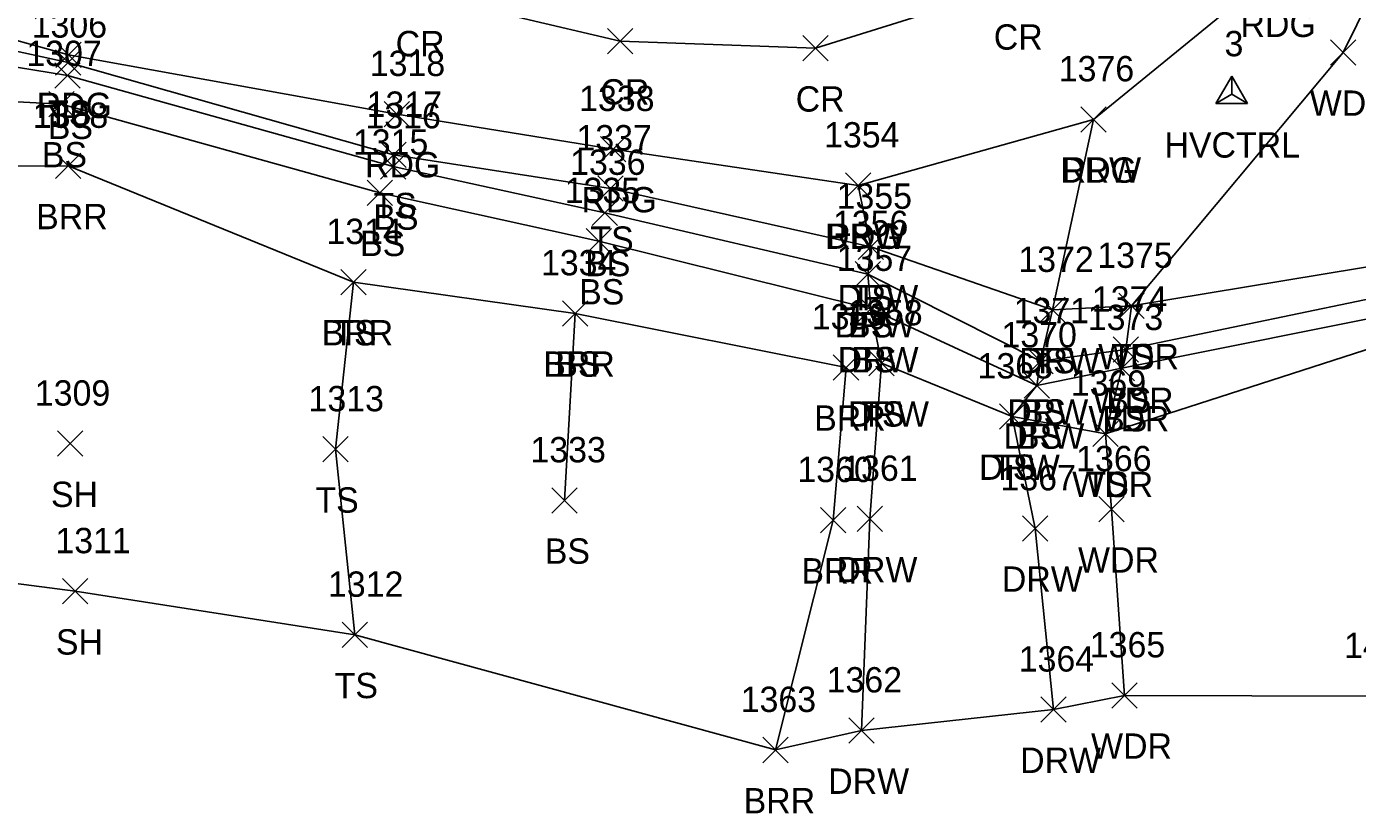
# Model space of a CAD drawing. Extents: x 1600281 to 1602254, y 862855 to 863227.
# Drawn here: x 1601927.2 to 1602032.3, y 862855.3 to 862917.4 of the extents above; entities that cross this region are included whole.
import ezdxf

# ---------------------------------------------------------------- set-up
doc = ezdxf.new("R2010")
doc.units = 0
for name, color, linetype in [('C_A', 7, 'Continuous'), ('C_I', 7, 'Continuous'), ('CPSM', 7, 'Continuous'), ('L_A', 7, 'Continuous'), ('L_I', 7, 'Continuous'), ('L_TIC', 7, 'Continuous'), ('LABL', 7, 'Continuous'), ('LAWA', 7, 'Continuous'), ('LELB', 7, 'Continuous'), ('LSOGP', 7, 'Continuous'), ('P_A', 7, 'Continuous'), ('P_I', 7, 'Continuous'), ('P_TIC', 7, 'Continuous'), ('PEU', 7, 'Continuous'), ('PRC', 7, 'Continuous'), ('R_A', 7, 'Continuous'), ('R_I', 7, 'Continuous'), ('R_TIC', 7, 'Continuous'), ('RDW', 7, 'Continuous')]:
    doc.layers.add(name, color=color, linetype=linetype)

msp = doc.modelspace()

# ---------------------------------------------------------------- linework, layer by layer
at = {"layer": 'CPSM'}
for p, q in [((1602021.09, 862911.32), (1602022.34, 862913.48)), ((1602023.59, 862911.32), (1602022.34, 862913.48)), ((1602022.34, 862912.04), (1602022.34, 862913.48)), ((1602021.09, 862911.32), (1602022.34, 862912.04)), ((1602022.34, 862912.04), (1602022.34, 862912.04)), ((1602022.34, 862912.04), (1602023.59, 862911.32)), ((1602021.09, 862911.32), (1602023.59, 862911.32))]:
    msp.add_line(p, q, dxfattribs=at)
at = {"layer": 'L_TIC'}
for points in [[(1602030.13, 862914.34), (1602032.13, 862916.34)], [(1602032.13, 862914.34), (1602030.13, 862916.34)], [(1601929.52, 862913.56), (1601931.52, 862915.56)], [(1601931.52, 862913.56), (1601929.52, 862915.56)], [(1601929.47, 862912.51), (1601931.47, 862914.51)], [(1601931.47, 862912.51), (1601929.47, 862914.51)], [(1601929, 862910.27), (1601931, 862912.27)], [(1601931, 862910.27), (1601929, 862912.27)], [(1601929.51, 862905.39), (1601931.51, 862907.39)], [(1601931.51, 862905.39), (1601929.51, 862907.39)], [(1601955.16, 862905.35), (1601957.16, 862907.35)], [(1601957.16, 862905.35), (1601955.16, 862907.35)], [(1601955.2, 862906.26), (1601957.2, 862908.26)], [(1601957.2, 862906.26), (1601955.2, 862908.26)], [(1601954.11, 862903.27), (1601956.11, 862905.27)], [(1601956.11, 862903.27), (1601954.11, 862905.27)], [(1601972.32, 862903.61), (1601974.32, 862905.61)], [(1601974.32, 862903.61), (1601972.32, 862905.61)], [(1601971.87, 862901.68), (1601973.87, 862903.68)], [(1601973.87, 862901.68), (1601971.87, 862903.68)], [(1601971.4, 862899.45), (1601973.4, 862901.45)], [(1601973.4, 862899.45), (1601971.4, 862901.45)], [(1601992.85, 862899), (1601994.85, 862901)], [(1601994.85, 862899), (1601992.85, 862901)], [(1601952.03, 862896.22), (1601954.03, 862898.22)], [(1601954.03, 862896.22), (1601952.03, 862898.22)], [(1601952.03, 862896.22), (1601954.03, 862898.22)], [(1601954.03, 862896.22), (1601952.03, 862898.22)], [(1601992.62, 862896.85), (1601994.62, 862898.85)], [(1601994.62, 862896.85), (1601992.62, 862898.85)], [(1601969.52, 862893.75), (1601971.52, 862895.75)], [(1601971.52, 862893.75), (1601969.52, 862895.75)], [(1601969.52, 862893.75), (1601971.52, 862895.75)], [(1601971.52, 862893.75), (1601969.52, 862895.75)], [(1601992.87, 862894.1), (1601994.87, 862896.1)], [(1601994.87, 862894.1), (1601992.87, 862896.1)], [(1602007.19, 862894.02), (1602009.19, 862896.02)], [(1602009.19, 862894.02), (1602007.19, 862896.02)], [(1602013.42, 862894.34), (1602015.42, 862896.34)], [(1602015.42, 862894.34), (1602013.42, 862896.34)], [(1602013.42, 862894.34), (1602015.42, 862896.34)], [(1602015.42, 862894.34), (1602013.42, 862896.34)], [(1602012.99, 862890.89), (1602014.99, 862892.89)], [(1602014.99, 862890.89), (1602012.99, 862892.89)], [(1602012.99, 862890.89), (1602014.99, 862892.89)], [(1602014.99, 862890.89), (1602012.99, 862892.89)], [(1601993.69, 862889.81), (1601995.69, 862891.81)], [(1601995.69, 862889.81), (1601993.69, 862891.81)], [(1602006.26, 862889.97), (1602008.26, 862891.97)], [(1602008.26, 862889.97), (1602006.26, 862891.97)], [(1601990.9, 862889.49), (1601992.9, 862891.49)], [(1601992.9, 862889.49), (1601990.9, 862891.49)], [(1602012.67, 862889.43), (1602014.67, 862891.43)], [(1602014.67, 862889.43), (1602012.67, 862891.43)], [(1602012.67, 862889.43), (1602014.67, 862891.43)], [(1602014.67, 862889.43), (1602012.67, 862891.43)], [(1602005.95, 862888.06), (1602007.95, 862890.06)], [(1602007.95, 862888.06), (1602005.95, 862890.06)], [(1602004.02, 862885.61), (1602006.02, 862887.61)], [(1602006.02, 862885.61), (1602004.02, 862887.61)], [(1601929.67, 862883.47), (1601931.67, 862885.47)], [(1601931.67, 862883.47), (1601929.67, 862885.47)], [(1602011.39, 862884.25), (1602013.39, 862886.25)], [(1602013.39, 862884.25), (1602011.39, 862886.25)], [(1602011.39, 862884.25), (1602013.39, 862886.25)], [(1602013.39, 862884.25), (1602011.39, 862886.25)], [(1601950.62, 862883.02), (1601952.62, 862885.02)], [(1601952.62, 862883.02), (1601950.62, 862885.02)], [(1601968.69, 862878.99), (1601970.69, 862880.99)], [(1601970.69, 862878.99), (1601968.69, 862880.99)], [(1602011.85, 862878.29), (1602013.85, 862880.29)], [(1602013.85, 862878.29), (1602011.85, 862880.29)], [(1601989.89, 862877.43), (1601991.89, 862879.43)], [(1601991.89, 862877.43), (1601989.89, 862879.43)], [(1601930.07, 862871.82), (1601932.07, 862873.82)], [(1601932.07, 862871.82), (1601930.07, 862873.82)], [(1601952.14, 862868.38), (1601954.14, 862870.38)], [(1601954.14, 862868.38), (1601952.14, 862870.38)], [(1602012.88, 862863.6), (1602014.88, 862865.6)], [(1602014.88, 862863.6), (1602012.88, 862865.6)], [(1601985.33, 862859.29), (1601987.33, 862861.29)], [(1601987.33, 862859.29), (1601985.33, 862861.29)]]:
    msp.add_lwpolyline(points, dxfattribs=at)
at = {"layer": 'LABL'}
msp.add_lwpolyline([(1601757.73, 862925.71), (1601782.73, 862922.12), (1601780.79, 862913), (1601791.17, 862907.66), (1601819.52, 862897.83), (1601840.22, 862897.63), (1601849.86, 862909.96), (1601871.21, 862909.53), (1601900.52, 862906.28), (1601930.51, 862906.39), (1601953.03, 862897.22), (1601970.52, 862894.75), (1601991.9, 862890.49), (1601990.89, 862878.43), (1601986.33, 862860.29)], dxfattribs=at)
at = {"layer": 'LAWA'}
msp.add_lwpolyline([(1602013.88, 862864.6), (1602012.85, 862879.29), (1602012.39, 862885.25), (1602013.67, 862890.43), (1602013.99, 862891.89), (1602014.42, 862895.34), (1602031.13, 862915.34), (1602041.82, 862937), (1602041.48, 862949.37), (1602043.12, 862970.37), (1602043.1, 862998.4), (1602042.78, 863006.72), (1602043.56, 863021.7), (1602048.72, 863030.45), (1602052.92, 863023.58), (1602057.07, 863015.5), (1602062.85, 863014.97)], dxfattribs=at)
at = {"layer": 'LELB'}
for points in [[(1601758.87, 862935.58), (1601794.57, 862931.04), (1601823.26, 862926.65), (1601871.56, 862921.03), (1601900.01, 862918.49), (1601930.47, 862913.51), (1601956.16, 862906.35), (1601972.87, 862902.68), (1601993.62, 862897.85), (1602007.26, 862890.97), (1602013.99, 862891.89), (1602036.74, 862896.62), (1602039.12, 862902.94), (1602042.65, 862913.22), (1602071.45, 862922.17), (1602077.73, 862924.94), (1602083, 862929.53), (1602079.85, 862943.1), (1602074.85, 862964.04), (1602072.57, 862980.37), (1602075.41, 862992.31), (1602081.73, 863011.09), (1602084.93, 863020.57), (1602086.17, 863023.52)], [(1601758.25, 862932.38), (1601793.25, 862926.87), (1601822.78, 862921.72), (1601870.88, 862915.2), (1601899.96, 862912.84), (1601930, 862911.27), (1601955.11, 862904.27), (1601972.4, 862900.45), (1601993.87, 862895.1), (1602006.95, 862889.06), (1602013.67, 862890.43), (1602037.38, 862895.19), (1602041.45, 862902.14), (1602044.34, 862911.83), (1602073.39, 862917.1), (1602080.57, 862918.06), (1602084.27, 862928.9), (1602082.1, 862942.17), (1602076.79, 862963.57), (1602077.84, 862979.48), (1602084.81, 862995.17), (1602084.83, 863009.34), (1602087.06, 863019.48), (1602088.42, 863022.64)], [(1601758.89, 862937.88), (1601795.07, 862933.9), (1601823.85, 862928.87), (1601870.34, 862922.92), (1601900.35, 862921.15), (1601930.52, 862914.56), (1601956.2, 862907.26), (1601973.32, 862904.61), (1601993.85, 862900), (1602008.19, 862895.02), (1602014.42, 862895.34), (1602035.61, 862898.84), (1602036.45, 862903.94), (1602042.39, 862916.03), (1602070.54, 862924.32), (1602075.87, 862928.13), (1602081.56, 862930.04), (1602078.85, 862942.66), (1602073.58, 862963.52), (1602071.23, 862980.75), (1602072.26, 862993.36), (1602076.69, 863007.7), (1602078.09, 863013.39), (1602083.85, 863020.87)], [(1601994.69, 862890.81), (1602005.02, 862886.61), (1602012.39, 862885.25), (1602036.93, 862893.17), (1602042.39, 862901.65), (1602044.79, 862907.83), (1602074.6, 862913.52), (1602080.81, 862915.53), (1602085.28, 862928.21), (1602083.54, 862943.15), (1602080.9, 862962.87), (1602080.76, 862979.18), (1602088.3, 862994.75), (1602086.85, 863009.16), (1602089.05, 863018.84)], [(1601953.14, 862869.38), (1601951.62, 862884.02), (1601953.03, 862897.22)], [(1601969.69, 862879.99), (1601970.52, 862894.75)]]:
    msp.add_lwpolyline(points, dxfattribs=at)
at = {"layer": 'LSOGP'}
msp.add_lwpolyline([(1601903.49, 862876.39), (1601931.07, 862872.82), (1601953.14, 862869.38), (1601986.33, 862860.29), (1601993.12, 862861.83), (1602008.27, 862863.48), (1602013.88, 862864.6), (1602033.97, 862864.54), (1602049.92, 862865.33), (1602074.24, 862873.53), (1602079.96, 862875.32), (1602087.74, 862877.95), (1602096.41, 862879.64), (1602098.44, 862879.18), (1602099.84, 862878.35), (1602105.22, 862879.24), (1602114.56, 862880.02)], dxfattribs=at)
at = {"layer": 'P_TIC'}
for points in [[(1601973.08, 862915.23), (1601975.08, 862917.23)], [(1601975.08, 862915.23), (1601973.08, 862917.23)], [(1601929.54, 862914.16), (1601931.54, 862916.16)], [(1601931.54, 862914.16), (1601929.54, 862916.16)], [(1601988.5, 862914.67), (1601990.5, 862916.67)], [(1601990.5, 862914.67), (1601988.5, 862916.67)], [(1601955.45, 862909.48), (1601957.45, 862911.48)], [(1601957.45, 862909.48), (1601955.45, 862911.48)], [(1602010.43, 862909.06), (1602012.43, 862911.06)], [(1602012.43, 862909.06), (1602010.43, 862911.06)], [(1601972.53, 862906.72), (1601974.53, 862908.72)], [(1601974.53, 862906.72), (1601972.53, 862908.72)], [(1601991.87, 862903.84), (1601993.87, 862905.84)], [(1601993.87, 862903.84), (1601991.87, 862905.84)]]:
    msp.add_lwpolyline(points, dxfattribs=at)
at = {"layer": 'PEU'}
msp.add_lwpolyline([(1601721.43, 862942.48), (1601759.39, 862940.42), (1601795.48, 862935.05), (1601824.44, 862931.28), (1601871.6, 862925.25), (1601900.95, 862923.39), (1601930.54, 862915.16), (1601956.45, 862910.48), (1601973.53, 862907.72), (1601992.87, 862904.84), (1602011.43, 862910.06), (1602025.54, 862921.56), (1602034.6, 862951.41), (1602037.17, 862973.14), (1602036.63, 863000.37), (1602039.38, 863008.7), (1602041.94, 863026.81), (1602046.4, 863038.48), (1602048.21, 863041.76), (1602041.55, 863045.82), (1602034.19, 863049.73), (1602032.2, 863046.61)], dxfattribs=at)
at = {"layer": 'PRC'}
msp.add_lwpolyline([(1601722.03, 862950.92), (1601760.35, 862947.65), (1601797.64, 862942.06), (1601826.1, 862939.87), (1601874.38, 862936.2), (1601906.56, 862932.66), (1601933.52, 862923.27), (1601957.93, 862920.04), (1601974.08, 862916.23), (1601989.5, 862915.67), (1602005.13, 862920.56), (1602020.05, 862931.21), (1602025.88, 862956.8), (1602029.68, 862975.25), (1602029.18, 863001.63), (1602032.15, 863012.73), (1602036.07, 863028.12), (1602041.55, 863045.82)], dxfattribs=at)
at = {"layer": 'R_TIC'}
for points in [[(1602010.43, 862909.06), (1602012.43, 862911.06)], [(1602012.43, 862909.06), (1602010.43, 862911.06)], [(1601991.87, 862903.84), (1601993.87, 862905.84)], [(1601993.87, 862903.84), (1601991.87, 862905.84)], [(1601992.85, 862899), (1601994.85, 862901)], [(1601994.85, 862899), (1601992.85, 862901)], [(1601992.62, 862896.85), (1601994.62, 862898.85)], [(1601994.62, 862896.85), (1601992.62, 862898.85)], [(1601992.87, 862894.1), (1601994.87, 862896.1)], [(1601994.87, 862894.1), (1601992.87, 862896.1)], [(1602007.19, 862894.02), (1602009.19, 862896.02)], [(1602009.19, 862894.02), (1602007.19, 862896.02)], [(1601993.69, 862889.81), (1601995.69, 862891.81)], [(1601995.69, 862889.81), (1601993.69, 862891.81)], [(1602006.26, 862889.97), (1602008.26, 862891.97)], [(1602008.26, 862889.97), (1602006.26, 862891.97)], [(1602005.95, 862888.06), (1602007.95, 862890.06)], [(1602007.95, 862888.06), (1602005.95, 862890.06)], [(1602004.02, 862885.61), (1602006.02, 862887.61)], [(1602006.02, 862885.61), (1602004.02, 862887.61)], [(1601992.78, 862877.53), (1601994.78, 862879.53)], [(1601994.78, 862877.53), (1601992.78, 862879.53)], [(1602005.83, 862876.78), (1602007.83, 862878.78)], [(1602007.83, 862876.78), (1602005.83, 862878.78)], [(1602007.27, 862862.48), (1602009.27, 862864.48)], [(1602009.27, 862862.48), (1602007.27, 862864.48)], [(1601992.12, 862860.83), (1601994.12, 862862.83)], [(1601994.12, 862860.83), (1601992.12, 862862.83)]]:
    msp.add_lwpolyline(points, dxfattribs=at)
at = {"layer": 'RDW'}
for points in [[(1602008.27, 862863.48), (1602006.83, 862877.78), (1602005.02, 862886.61), (1602006.95, 862889.06), (1602007.26, 862890.97), (1602008.19, 862895.02), (1602011.43, 862910.06)], [(1601992.87, 862904.84), (1601993.85, 862900), (1601993.62, 862897.85), (1601993.87, 862895.1), (1601994.69, 862890.81), (1601993.78, 862878.53), (1601993.12, 862861.83)]]:
    msp.add_lwpolyline(points, dxfattribs=at)

# ---------------------------------------------------------------- texts
at = {"layer": 'C_A'}
msp.add_text('HVCTRL', height=2, dxfattribs=at).set_placement((1602017.03, 862907.04))
at = {"layer": 'C_I'}
msp.add_text('3', height=2, dxfattribs=at).set_placement((1602021.77, 862915.04))
at = {"layer": 'L_A'}
for s, p in [('TS', (1601928.93, 862909.56)), ('WDR', (1602028.5, 862910.34)), ('BS', (1601928.91, 862908.51)), ('BS', (1601928.44, 862906.27)), ('TS', (1601954.61, 862902.26)), ('BRR', (1601927.99, 862901.39)), ('BS', (1601954.6, 862901.35)), ('BS', (1601953.55, 862899.27)), ('TS', (1601971.73, 862899.61)), ('BS', (1601971.32, 862897.68)), ('BS', (1601970.84, 862895.45)), ('TS', (1601992.26, 862895)), ('BS', (1601992.06, 862892.85)), ('BRR', (1601950.52, 862892.22)), ('TS', (1601951.44, 862892.22)), ('BRR', (1601968.01, 862889.75)), ('BS', (1601968.96, 862889.75)), ('BS', (1601992.31, 862890.1)), ('TS', (1602006.6, 862890.02)), ('WDR', (1602011.79, 862890.34)), ('TS', (1602012.83, 862890.34)), ('WDR', (1602011.36, 862886.89)), ('BS', (1602012.43, 862886.89)), ('BRR', (1601989.39, 862885.49)), ('TS', (1601993.1, 862885.81)), ('BS', (1602005.7, 862885.97)), ('WDR', (1602011.03, 862885.43)), ('BS', (1602012.11, 862885.43)), ('BS', (1602005.39, 862884.06)), ('TS', (1602003.43, 862881.61)), ('WDR', (1602009.75, 862880.25)), ('TS', (1602010.8, 862880.25)), ('SH', (1601929.16, 862879.47)), ('TS', (1601950.03, 862879.02)), ('BS', (1601968.13, 862874.99)), ('WDR', (1602010.21, 862874.29)), ('BRR', (1601988.38, 862873.43)), ('SH', (1601929.55, 862867.82)), ('TS', (1601951.55, 862864.38)), ('WDR', (1602011.24, 862859.6)), ('BRR', (1601983.82, 862855.29))]:
    msp.add_text(s, height=2, dxfattribs=at).set_placement(p)
at = {"layer": 'L_I'}
for s, p in [('1306', (1601927.64, 862916.51)), ('1307', (1601927.22, 862914.27)), ('1317', (1601954.07, 862910.26)), ('1308', (1601927.73, 862909.39)), ('1316', (1601953.98, 862909.35)), ('1337', (1601970.63, 862907.61)), ('1315', (1601952.99, 862907.27)), ('1336', (1601970.13, 862905.68)), ('1335', (1601969.7, 862903.45)), ('1355', (1601991.16, 862903)), ('1314', (1601950.9, 862900.22)), ('1314', (1601950.9, 862900.22)), ('1356', (1601990.87, 862900.85)), ('1357', (1601991.17, 862898.1)), ('1372', (1602005.5, 862898.02)), ('1375', (1602011.73, 862898.34)), ('1375', (1602011.73, 862898.34)), ('1334', (1601967.83, 862897.75)), ('1334', (1601967.83, 862897.75)), ('1374', (1602011.3, 862894.89)), ('1374', (1602011.3, 862894.89)), ('1358', (1601992, 862893.81)), ('1371', (1602005.13, 862893.97)), ('1359', (1601989.2, 862893.49)), ('1373', (1602010.98, 862893.43)), ('1373', (1602010.98, 862893.43)), ('1370', (1602004.17, 862892.06)), ('1368', (1602002.28, 862889.61)), ('1309', (1601927.89, 862887.47)), ('1369', (1602009.64, 862888.25)), ('1369', (1602009.64, 862888.25)), ('1313', (1601949.49, 862887.02)), ('1333', (1601967, 862882.99)), ('1366', (1602010.06, 862882.29)), ('1360', (1601988.06, 862881.43)), ('1311', (1601929.51, 862875.82)), ('1312', (1601951.02, 862872.38)), ('1365', (1602011.14, 862867.6)), ('1402', (1602031.2, 862867.54)), ('1363', (1601983.59, 862863.29))]:
    msp.add_text(s, height=2, dxfattribs=at).set_placement(p)
at = {"layer": 'P_A'}
for s, p in [('RDG', (1602023.03, 862916.56)), ('CR', (1601956.36, 862915.04)), ('CR', (1602003.56, 862915.56)), ('CR', (1601972.52, 862911.23)), ('CR', (1601987.93, 862910.67)), ('RDG', (1601928.03, 862910.16)), ('RDG', (1601953.94, 862905.48)), ('RDG', (1602008.92, 862905.06)), ('RDG', (1601971.02, 862902.72)), ('RDG', (1601990.35, 862899.84))]:
    msp.add_text(s, height=2, dxfattribs=at).set_placement(p)
at = {"layer": 'P_I'}
for s, p in [('1318', (1601954.32, 862913.48)), ('1376', (1602008.69, 862913.06)), ('1338', (1601970.84, 862910.72)), ('1354', (1601990.17, 862907.84))]:
    msp.add_text(s, height=2, dxfattribs=at).set_placement(p)
at = {"layer": 'R_A'}
for p in [(1602008.8, 862905.06), (1601990.24, 862899.84), (1601991.22, 862895), (1601990.99, 862892.85), (1601991.24, 862890.1), (1602005.56, 862890.02), (1601992.06, 862885.81), (1602004.63, 862885.97), (1602004.32, 862884.06), (1602002.39, 862881.61), (1601991.15, 862873.53), (1602004.2, 862872.78), (1602005.64, 862858.48), (1601990.49, 862856.83)]:
    msp.add_text('DRW', height=2, dxfattribs=at).set_placement(p)
at = {"layer": 'R_I'}
for s, p in [('1376', (1602008.69, 862913.06)), ('1354', (1601990.17, 862907.84)), ('1355', (1601991.16, 862903)), ('1356', (1601990.87, 862900.85)), ('1357', (1601991.17, 862898.1)), ('1372', (1602005.5, 862898.02)), ('1358', (1601992, 862893.81)), ('1371', (1602005.13, 862893.97)), ('1370', (1602004.17, 862892.06)), ('1368', (1602002.28, 862889.61)), ('1361', (1601991.6, 862881.53)), ('1367', (1602004.09, 862880.78)), ('1364', (1602005.53, 862866.48)), ('1362', (1601990.37, 862864.83))]:
    msp.add_text(s, height=2, dxfattribs=at).set_placement(p)

doc.saveas('drawing.dxf')
